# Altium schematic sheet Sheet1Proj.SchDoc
size A4; SheetNumber: 1; SheetTotal: 1
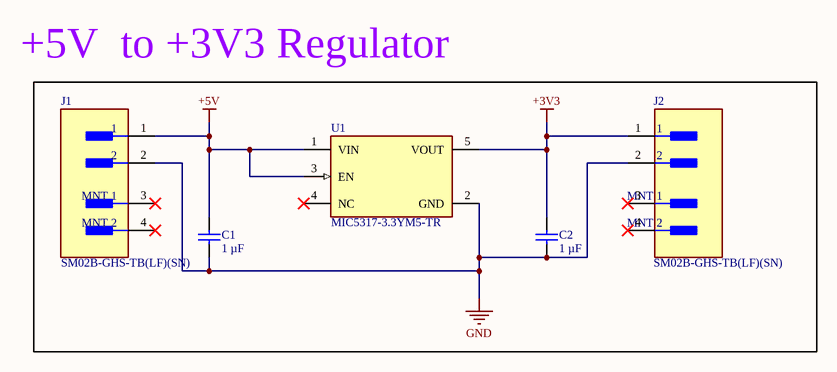
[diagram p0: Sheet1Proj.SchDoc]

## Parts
C1  1 µF  [CAPC2013X145X50NL20T20]
C2  1 µF  [CAPC2013X145X50NL20T20]
J1  SM02B-GHS-TB(LF)(SN)  [FP-SM02B-GHS-TB_LF_SN-MFG]
J2  SM02B-GHS-TB(LF)(SN)  [FP-SM02B-GHS-TB_LF_SN-MFG]
U1  MIC5317-3.3YM5-TR  [FP-SOT23-5LD-PL-1-MFG]

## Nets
+3V3: C2.2 J2.1 U1.5(VOUT)
+5V: C1.2 J1.1 U1.1(VIN) U1.3(EN)
GND: C1.1 C2.1 J1.2 J2.2 U1.2(GND)

Not connected (* = marked no-connect by the designer): J1 3(MNT_1)* 4(MNT_2)*; J2 3(MNT_1)* 4(MNT_2)*; U1 4(NC)*

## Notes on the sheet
- +5V  to +3V3 Regulator

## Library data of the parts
C1 C2 = CMP-2007-01676-1: Part Number: VJ0805Y105KXQRW1BC; Manufacturer: Vitramon
J1 J2 = CMP-2000-07076-2: CONN HEADER SMD R/A 2POS 1.25MM; Voltage Rating: 50V; Number of Positions: 2; Pitch: 0.049inch; Current Rating: 1A; Connector Type: Outer Shroud Contact
U1 = CMP-06324-000116-1: IC REG LINEAR 3.3V 150MA SOT23-5; Max Input Voltage: 6V; Number of Regulators: 1; Min Current Limit: 200mA; Dropout Voltage: 155mV; Min Input Voltage: 2.5V; Power Supply Rejection Ratio (PSRR): 70dB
